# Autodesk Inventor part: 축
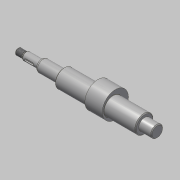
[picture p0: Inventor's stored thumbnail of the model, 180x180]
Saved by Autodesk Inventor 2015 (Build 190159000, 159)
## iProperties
Created: 2015-12
Part Number: 축
Document SubType Name: Modeling
Designer: mdu
Density: 7.86 g/cm^3
Material: 강철, 연강
Appearance: 강철
Mass: 484.678 g
Surface Area: 125.968 cm^2
Volume: 61.6639 cm^3
Author: mdu
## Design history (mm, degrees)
sketch "스케치1"
  geometry: L1 (62, 100.9)-(62, 67.1) reference; L2 (51, 101.2)-(51, 84) reference; L3 (-51, 84)-(-51, 101.2) reference; L4 (-62, 67.1)-(-62, 100.9) reference; L5 (-51.6, 91.5)-(-61.4, 91.5) reference; L6 (51.6, 91.5)-(61.4, 91.5) reference; L7 (67, 84)-(-109, 84); L8 (-77, 64.201)-(-77, 103.799) reference; L9 (67, 84)-(67, 91.5); L10 (67, 91.5)-(51, 91.5); L11 (51, 91.5)-(51, 95.5); L12 (51, 95.5)-(-51, 95.5); L13 (-51, 95.5)-(-51, 91.5); L14 (-51, 91.5)-(-79, 91.5); L15 (-79, 91.5)-(-79, 89); L16 (-79, 89)-(-99, 89); L17 (-99, 89)-(-99, 87); L18 (-100.5, 88)-(-109, 88); L19 (-109, 88)-(-109, 84); L20 (-99, 87)-(-100.5, 87); L21 (-100.5, 87)-(-100.5, 88); 2 further points
  constraints: 32 end point, 7 parallel, 6 point on line, 5 perpendicular, 2 collinear, 2 horizontal, 1 midpoint, 4 other
  dimensions: "d0" = 5 distance from line of L7.start L1; "d2" = 2 distance between parallel lines of L15 L8; "d3" = 23 diameter of L12 L7; "d4" = 10 diameter of L16 L7; "d5" = 1.5 distance of L17.end L20.end; "d6" = 6 diameter of L20 L7; "d7" = 20 distance of L15.end L16.end; "d8" = 10 distance between parallel lines of L17 L19; "d9" = 8 diameter of L18 L7
revolve "회전1" sketch "스케치1" stored, may be unused: angle "d10" = 90 deg
sketch "스케치2"
  geometry: C1 r 11.5 at (84, 0) reference; C2 r 11.5 at (84, 0) reference; C3 r 16.5 at (87, 0); 1 further point
  constraints: 1 centre point, 1 horizontal alignment
  dimensions: "d11" = 33 diameter of C3; "d12" = 3 distance of C3.centre C1.centre
extrude "돌출1" join sketch "스케치2" stored distance "d13" = 22; taper "d14" = 0 deg
chamfer "모따기1" distance "d15" = 1; stored, may be unused: second distance "d16" = 2, angle "d17" = 45 deg
feature "스레드1" dims "d18" = 10, "d19" = 0
node "작업 평면1"
sketch "스케치3"
  geometry: L1 (-5.5, -1.5)-(3.5, -1.5); L2 (3.5, 1.5)-(-5.5, 1.5); L3 (-10, -4)-(-10, 4) reference; A1 r 1.5 centre (3.5, 0) between (3.5, -1.5) and (3.5, 1.5); A2 r 1.5 centre (-5.5, 0) between (-5.5, 1.5) and (-5.5, -1.5); 2 further points
  constraints: 4 end point, 4 point on circle, 4 tangent, 2 centre point, 1 horizontal, 1 horizontal alignment, 1 midpoint, 1 parallel
  dimensions: "d20" = 3 distance between parallel lines of L1 L2; "d21" = 12 dimension on A1 A2; "d22" = 3 distance edge to line of A2 L3
extrude "돌출2" cut sketch "스케치3" distance "d23" = 1.8; taper "d24" = 0 deg
fillet "모깎기1" dims "d25" = 0.3
fillet "모깎기2" dims "d26" = 3
node "솔리드1"
node "참조1"
node "참조2"
node "참조3"
node "참조4"
node "참조5"
node "투영된 루프1"
